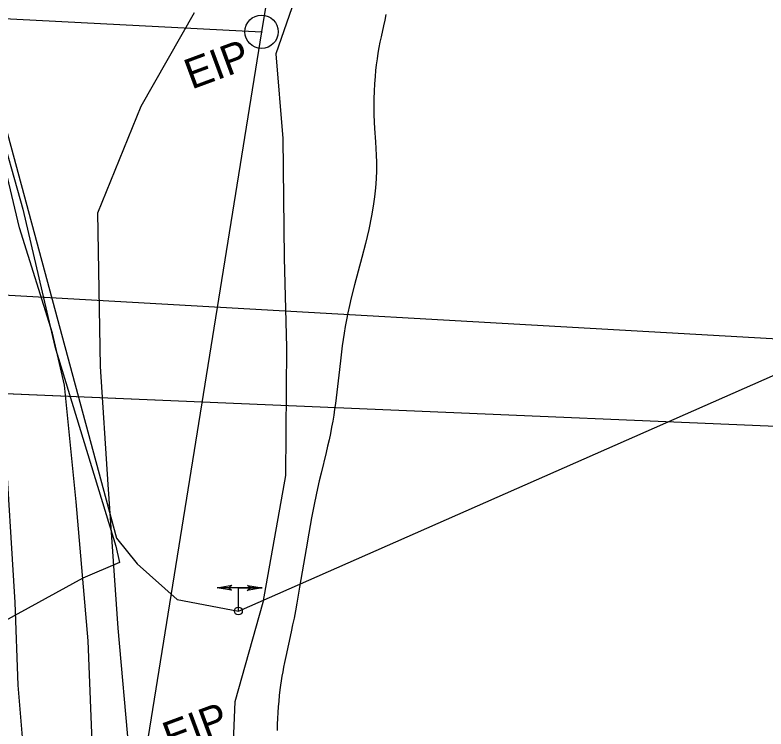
# Model space of a CAD drawing. Extents: x 2597630 to 2605918, y 617194 to 635093.
# Drawn here: x 2604035.3 to 2604134.7, y 618461.9 to 618556.4 of the extents above; entities that cross this region are included whole.
import ezdxf

# ---------------------------------------------------------------- set-up
doc = ezdxf.new("R2010")
doc.units = 0
for name, color, linetype in [('COGO Default Chain', 7, 'Continuous'), ('Exist Hydro Stream or Body of Water', 7, 'Continuous'), ('Exist Property Iron Pin CELL', 7, 'Continuous'), ('Exist Property Iron Pin Text', 7, 'Continuous'), ('Exist Property Line', 7, 'Continuous'), ('Exist Right of Way Line', 7, 'Continuous'), ('Exist Roads EOP', 7, 'Continuous'), ('Exist Roads Soil', 7, 'Continuous'), ('Exist Utilities Power Change of Service SUE CELL', 7, 'Continuous'), ('Exist Utilities Power UG Cable SUE LOS B', 7, 'Continuous'), ('Exist Utilities Power UG Cable SUE LOS C', 7, 'Continuous'), ('Exist Vegetation Woods Line', 7, 'Continuous')]:
    doc.layers.add(name, color=color, linetype=linetype)

# ---------------------------------------------------------------- blocks, each defined once
blk = doc.blocks.new('EXIST PROPERTY IRON PIN')
at = {"layer": 'Exist Property Iron Pin CELL'}
for radius in [0.0441, 0.00141]:
    blk.add_circle((0, 0), radius, dxfattribs=at)

msp = doc.modelspace()

# ---------------------------------------------------------------- linework, layer by layer
at = {"layer": 'COGO Default Chain'}
for p, q in [((2603941.678, 618524.592), (2605203.918, 618452.701)), ((2603949.703, 618509.809), (2604060.01, 618505.175)), ((2603949.703, 618509.809), (2605085.762, 618462.08)), ((2603949.703, 618509.809), (2605085.762, 618462.08))]:
    msp.add_line(p, q, dxfattribs=at)
at = {"layer": 'Exist Hydro Stream or Body of Water'}
msp.add_lwpolyline([(2604084.35, 618556.45), (2604084.195, 618555.685), (2604084.034, 618554.944), (2604083.714, 618553.509), (2604083.565, 618552.805), (2604083.421, 618552.06), (2604083.292, 618551.315), (2604083.178, 618550.564), (2604083.078, 618549.807), (2604082.992, 618549.039), (2604082.919, 618548.259), (2604082.847, 618547.281), (2604082.794, 618546.284), (2604082.763, 618545.273), (2604082.753, 618544.254), (2604082.766, 618543.23), (2604082.802, 618542.208), (2604082.851, 618541.339), (2604082.973, 618539.597), (2604083.03, 618538.715), (2604083.076, 618537.821), (2604083.101, 618536.91), (2604083.097, 618535.811), (2604083.054, 618534.68), (2604082.968, 618533.515), (2604082.839, 618532.313), (2604082.665, 618531.073), (2604082.442, 618529.791), (2604082.067, 618527.994), (2604081.628, 618526.15), (2604081.151, 618524.292), (2604080.194, 618520.664), (2604079.767, 618518.959), (2604079.533, 618517.948), (2604079.323, 618516.979), (2604079.137, 618516.046), (2604078.971, 618515.146), (2604078.823, 618514.274), (2604078.692, 618513.426), (2604078.575, 618512.604), (2604078.469, 618511.8), (2604078.373, 618511.009), (2604078.198, 618509.46), (2604077.949, 618507.205), (2604077.769, 618505.719), (2604077.671, 618504.974), (2604077.564, 618504.227), (2604077.441, 618503.436), (2604077.306, 618502.637), (2604077.158, 618501.829), (2604076.997, 618501.009), (2604076.821, 618500.173), (2604076.629, 618499.319), (2604076.428, 618498.47), (2604075.761, 618495.742), (2604075.527, 618494.752), (2604075.292, 618493.71), (2604074.902, 618491.835), (2604074.52, 618489.848), (2604074.149, 618487.8), (2604073.791, 618485.742), (2604072.93, 618480.661), (2604072.557, 618478.531), (2604072.374, 618477.534), (2604072.191, 618476.576), (2604072.006, 618475.652), (2604071.818, 618474.767), (2604071.085, 618471.463), (2604070.92, 618470.68), (2604070.801, 618470.073), (2604070.689, 618469.471), (2604070.585, 618468.871), (2604070.49, 618468.27), (2604070.402, 618467.667), (2604070.323, 618467.059), (2604070.237, 618466.321), (2604070.163, 618465.574), (2604070.098, 618464.82), (2604070.044, 618464.058), (2604070, 618463.292), (2604069.965, 618462.522), (2604069.938, 618461.678)], dxfattribs=at)
at = {"layer": 'Exist Property Line'}
msp.add_line((2604078.353, 618616.69), (2604067.887, 618554.168), dxfattribs=at)
at = {"layer": 'Exist Right of Way Line'}
for p, q in [((2603986.178, 618558.327), (2604067.887, 618554.168)), ((2604067.887, 618554.168), (2604051.903, 618454.756))]:
    msp.add_line(p, q, dxfattribs=at)
at = {"layer": 'Exist Roads EOP'}
msp.add_spline([(2603230.17, 618389.98), (2603282.929, 618409.597), (2603332.773, 618427.868), (2603388.167, 618448.413), (2603437.203, 618466.721), (2603490.778, 618486.527), (2603539.039, 618504.558), (2603597.451, 618526.156), (2603651.053, 618545.972), (2603705.208, 618566.084), (2603762.02, 618587.183), (2603820.334, 618609.162), (2603876.341, 618629.99), (2603934.909, 618652.28), (2603996.409, 618675.568), (2604033.216, 618689.957), (2604052.01, 618697.199)], degree=3, dxfattribs=at)
at = {"layer": 'Exist Roads Soil'}
for points in [[(2604045.714, 618453.546), (2604044.946, 618473.566), (2604043.333, 618491.969), (2604041.8, 618507.386), (2604040.227, 618514.293), (2604035.859, 618528.229), (2604032.582, 618541.816), (2604027.277, 618554.564), (2604019.525, 618571.495), (2604012.48, 618586.034), (2604006.554, 618597.689), (2603992.13, 618636.179), (2603991.872, 618638.982), (2603991.977, 618641.654), (2603992.516, 618646.05), (2603993.333, 618649.771), (2603994.254, 618652.361), (2603995.659, 618654.099)], [(2604039.099, 618441.937), (2604036.671, 618455.507), (2604035.673, 618467.671), (2604035.277, 618478.62), (2604033.892, 618500.873), (2604030.61, 618514.776), (2604025.18, 618530.601), (2604016.09, 618553.807), (2604008.263, 618573.362), (2604002.452, 618586.829), (2603981.38, 618632.847), (2603979.807, 618635.771), (2603978.555, 618638.427), (2603977.233, 618639.272), (2603974.326, 618640.189), (2603971.149, 618640.923), (2603968.018, 618641.656), (2603964.389, 618642.324)]]:
    msp.add_lwpolyline(points, dxfattribs=at)
at = {"layer": 'Exist Utilities Power Change of Service SUE CELL'}
for p, q in [((2604067.96, 618480.579), (2604061.998, 618480.579)), ((2604064.825, 618477.494), (2604064.825, 618480.579)), ((2604064.825, 618480.579), (2604067.96, 618480.579)), ((2604064.825, 618477.494), (2604064.825, 618477.494))]:
    msp.add_line(p, q, dxfattribs=at)
for points in [[(2604061.998, 618480.579), (2604063.969, 618480.923), (2604063.549, 618480.579), (2604063.93, 618480.273)], [(2604067.96, 618480.579), (2604065.99, 618480.235), (2604066.41, 618480.579), (2604066.028, 618480.884)]]:
    msp.add_lwpolyline(points, close=True, dxfattribs=at)
msp.add_circle((2604064.825, 618477.494), 0.517, dxfattribs=at)
at = {"layer": 'Exist Utilities Power UG Cable SUE LOS B'}
for points in [[(2603864.631, 618522.005), (2603884.048, 618524.916), (2603913.334, 618530.826), (2603929.804, 618535.758), (2603954.494, 618540.204), (2603987.674, 618545.635), (2604011.291, 618547.786), (2604023.001, 618547.185), (2604029.279, 618545.047), (2604030.821, 618545.321), (2604032.732, 618544.529), (2604033.333, 618544.105), (2604048.684, 618487.131), (2604051.412, 618483.753), (2604056.728, 618479.032), (2604064.825, 618477.494)], [(2604032.857, 618542.793), (2604036.304, 618530.671), (2604040.51, 618512.51), (2604048.576, 618486.083), (2604049.085, 618483.935), (2604044.243, 618481.855), (2604033.358, 618475.873)]]:
    msp.add_lwpolyline(points, dxfattribs=at)
at = {"layer": 'Exist Utilities Power UG Cable SUE LOS C'}
msp.add_line((2604064.825, 618477.494), (2604726.279, 618768.764), dxfattribs=at)
at = {"layer": 'Exist Vegetation Woods Line'}
for points in [[(2604077.83, 618574.35), (2604069.779, 618551.235), (2604070.706, 618540.053), (2604070.886, 618524.227), (2604071.18, 618512.398), (2604071.053, 618495.449), (2604068.047, 618478.627), (2604064.36, 618465.474), (2604063.851, 618453.957), (2604064.045, 618424.234)], [(2604056.613, 618415.662), (2604056.218, 618422.213), (2604052.557, 618434.802), (2604051.455, 618447.42), (2604050.364, 618458.92), (2604048.9, 618475.211), (2604047.564, 618494.223), (2604046.587, 618509.88), (2604046.196, 618530.181), (2604051.95, 618544.317), (2604059.004, 618556.708)]]:
    msp.add_lwpolyline(points, dxfattribs=at)

# ---------------------------------------------------------------- block references
at = {"layer": 'Exist Property Iron Pin CELL', "xscale": 50, "yscale": 50}
msp.add_blockref('EXIST PROPERTY IRON PIN', (2604067.887, 618554.168), dxfattribs=at)

# ---------------------------------------------------------------- texts
at = {"layer": 'Exist Property Iron Pin Text'}
for p in [(2604058.623, 618546.498), (2604055.769, 618458.757)]:
    msp.add_text('EIP', height=4, rotation=20.32212, dxfattribs=at).set_placement(p)

doc.saveas('drawing.dxf')
